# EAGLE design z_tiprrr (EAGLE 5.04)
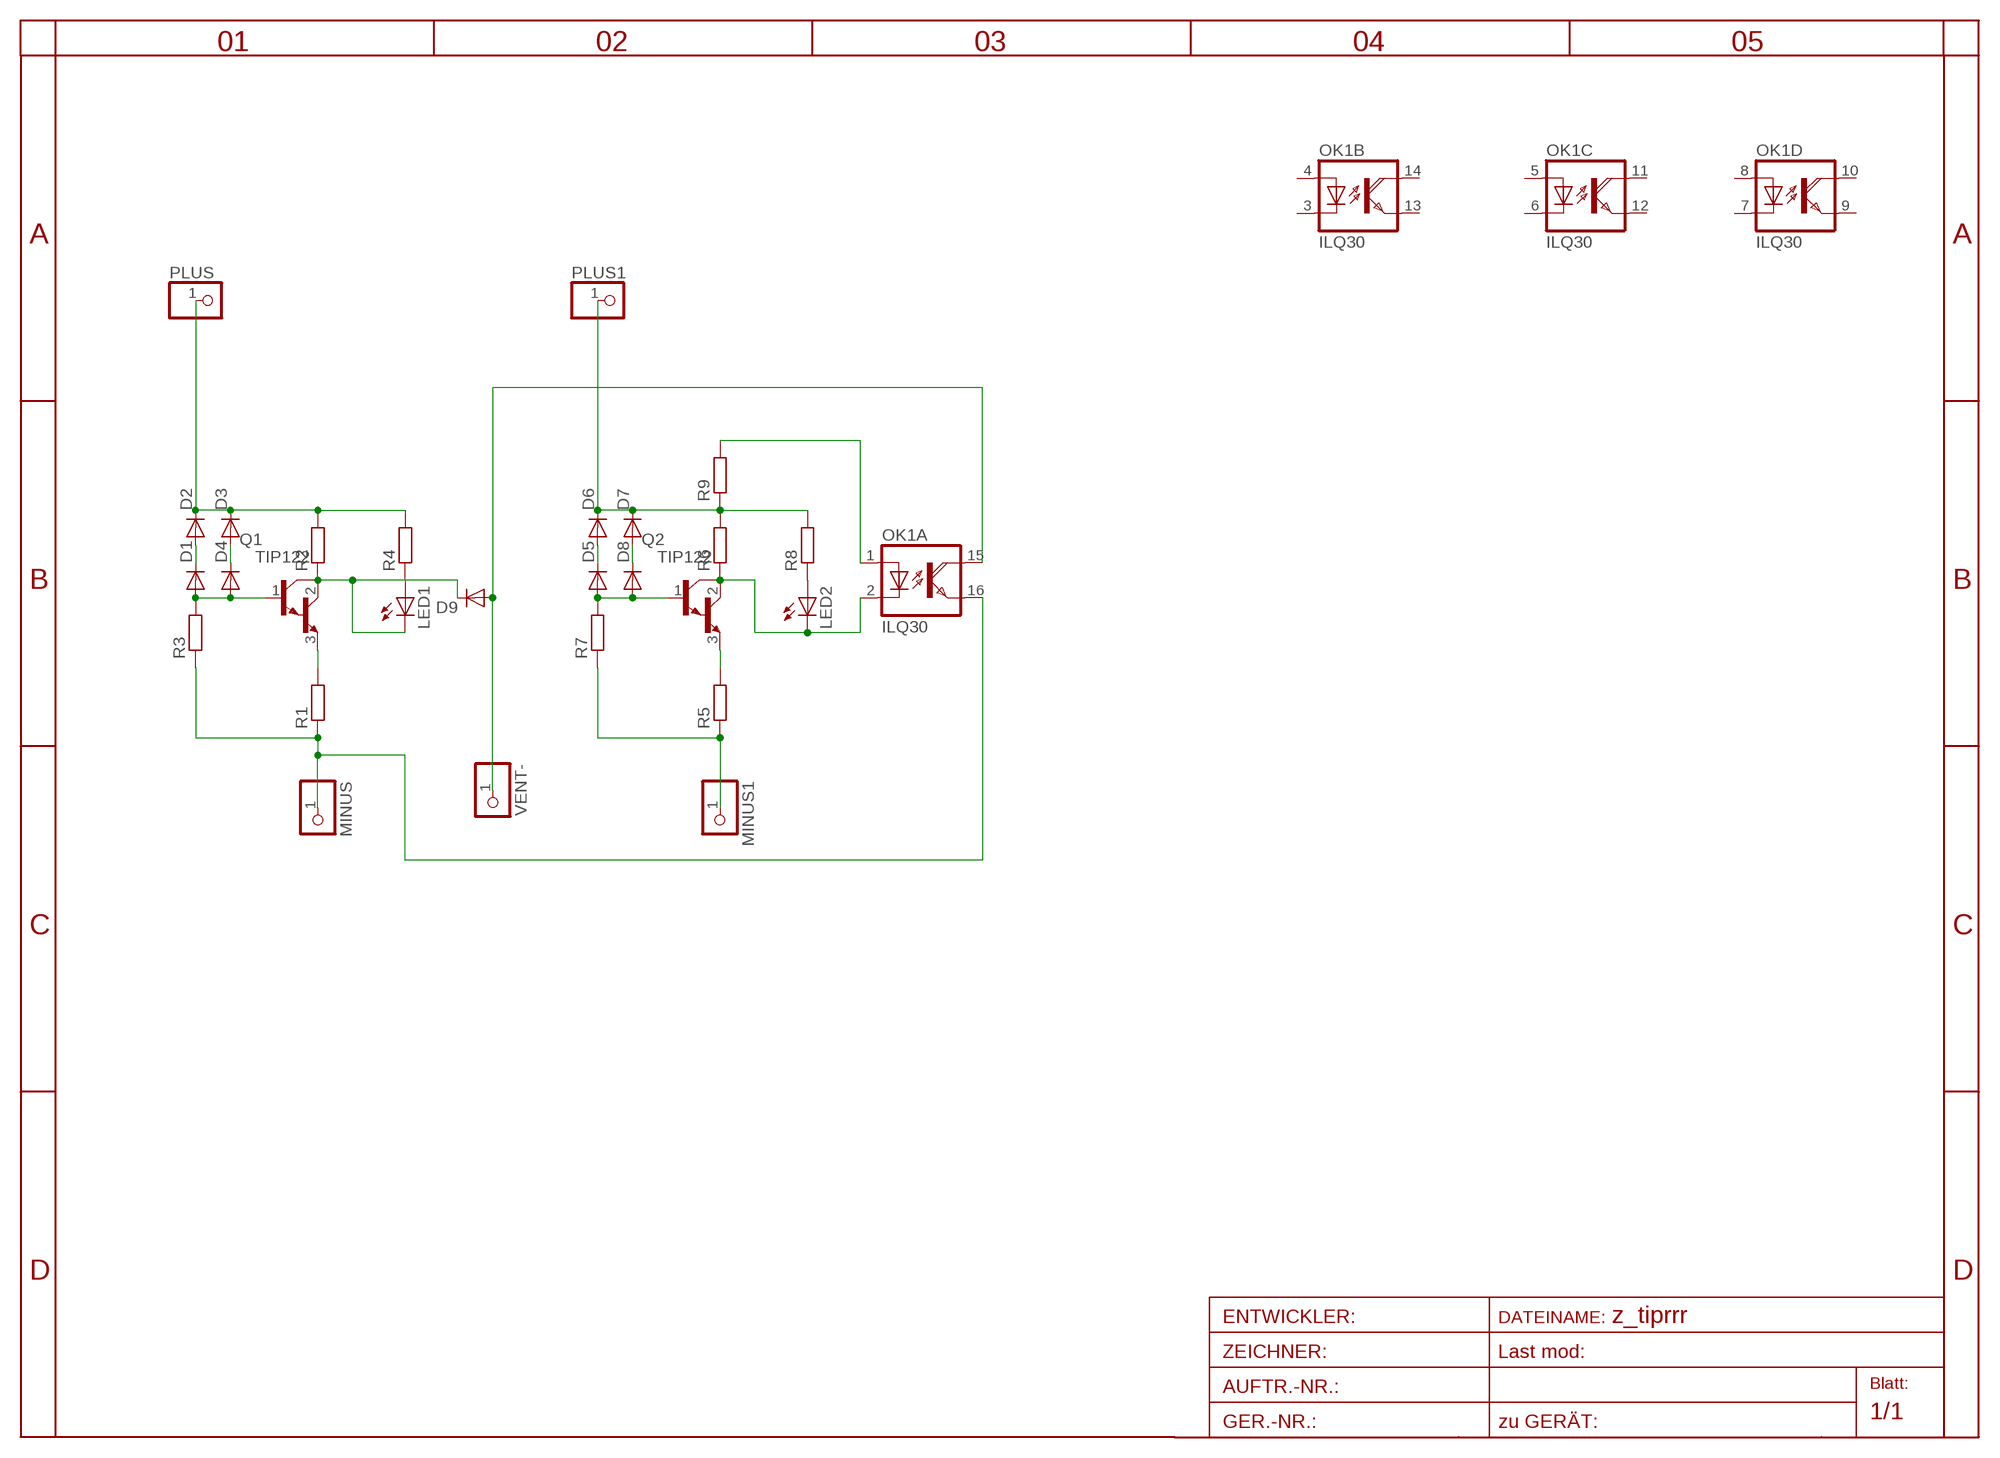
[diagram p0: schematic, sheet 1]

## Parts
D1  DIODE-MINIMELF  [MINIMELF]
D2  DIODE-MINIMELF  [MINIMELF]
D3  DIODE-D-2.5  [D-2.5]
D4  DIODE-D-2.5  [D-2.5]
D5  DIODE-MINIMELF  [MINIMELF]
D6  DIODE-MINIMELF  [MINIMELF]
D7  DIODE-D-2.5  [D-2.5]
D8  DIODE-D-2.5  [D-2.5]
D9  DIODE-MINIMELF  [MINIMELF]
LED1  LED3MM  [LED3MM]
LED2  LED3MM  [LED3MM]
MINUS  PINHD-1X1  [1X01]
MINUS1  PINHD-1X1  [1X01]
OK1  ILQ30  [DIL16]
PLUS  PINHD-1X1  [1X01]
PLUS1  PINHD-1X1  [1X01]
Q1  TIP122  [TO220]
Q2  TIP122  [TO220]
R1  R-EU_M3216  [M3216]
R2  R-EU_M3216  [M3216]
R3  R-EU_R0805  [R0805]
R4  R-EU_M0805  [M0805]
R5  R-EU_M3216  [M3216]
R6  R-EU_M3216  [M3216]
R7  R-EU_R0805  [R0805]
R8  R-EU_M3216  [M3216]
R9  R-EU_M0805  [M0805]
VENT-  PINHD-1X1  [1X01]

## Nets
N$1: D3.A D4.C
N$2: D1.C D2.A
N$3: OK1.1(A:A) R9.2
N$4: D1.A D4.A Q1.1(B) R3.2
N$5: LED1.A R4.1
N$6: MINUS.1 OK1.16(A:EMI) R1.1 R3.1
N$7: Q1.3(E) R1.2
N$8: D9.A OK1.15(A:COL) VENT-.1
N$9: MINUS1.1 R5.1 R7.1
N$10: D5.C D6.A
N$11: D5.A D8.A Q2.1(B) R7.2
N$12: D7.A D8.C
N$13: LED2.K(C) OK1.2(A:C) Q2.2(C) R6.1
N$14: Q2.3(E) R5.2
N$15: LED2.A R8.1
N$16: D9.C LED1.K(C) Q1.2(C) R2.1
PLS: D2.C D3.C PLUS.1 R2.2 R4.2
PLS1: D6.C D7.C PLUS1.1 R6.2 R8.2 R9.1
Unconnected: OK1.3(B:C) OK1.4(B:A) OK1.5(C:A) OK1.6(C:C) OK1.7(D:C) OK1.8(D:A) OK1.9(D:EMI) OK1.10(D:COL) OK1.11(C:COL) OK1.12(C:EMI) OK1.13(B:EMI) OK1.14(B:COL)

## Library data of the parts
D1-D9 = diode-1:DIODE-: DIODE
LED1 LED2 = led:LED: LED
MINUS MINUS1 PLUS PLUS1 VENT- = pinhead:PINHD-1X1: PIN HEADER
OK1 = optocoupler:ILQ30: SIEMENS OPTO COUPLER
Q1 Q2 = transistor-npn:TIP122*: NPN Darlington Transistor
R1-R9 = rcl:R-EU_: RESISTOR, European symbol

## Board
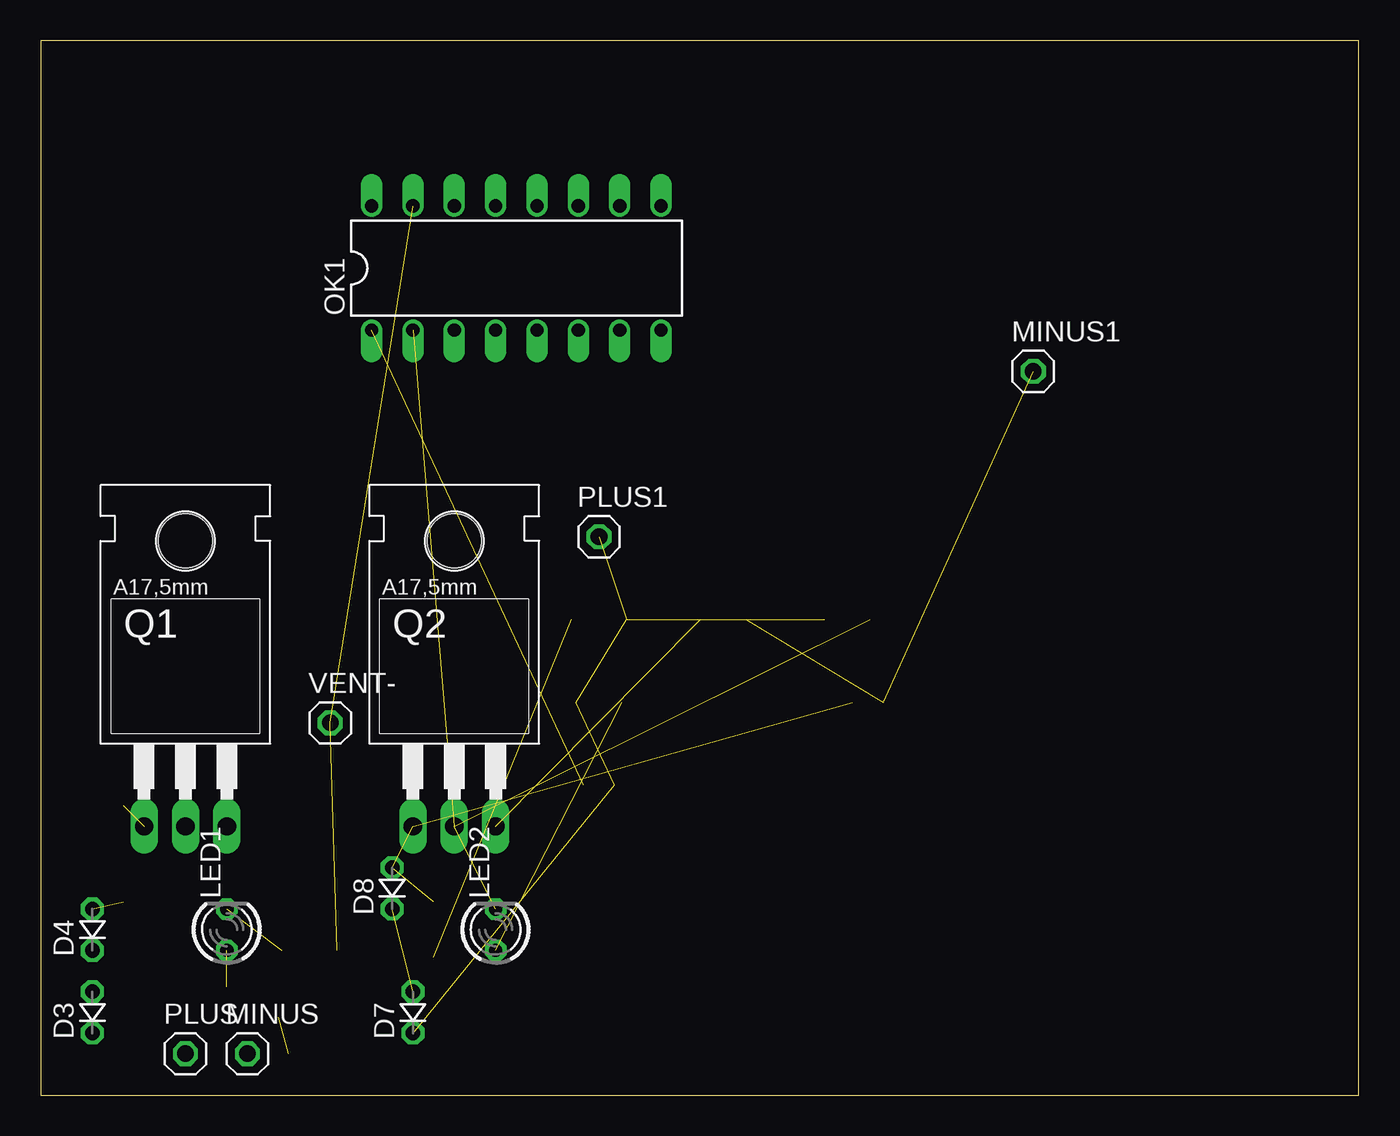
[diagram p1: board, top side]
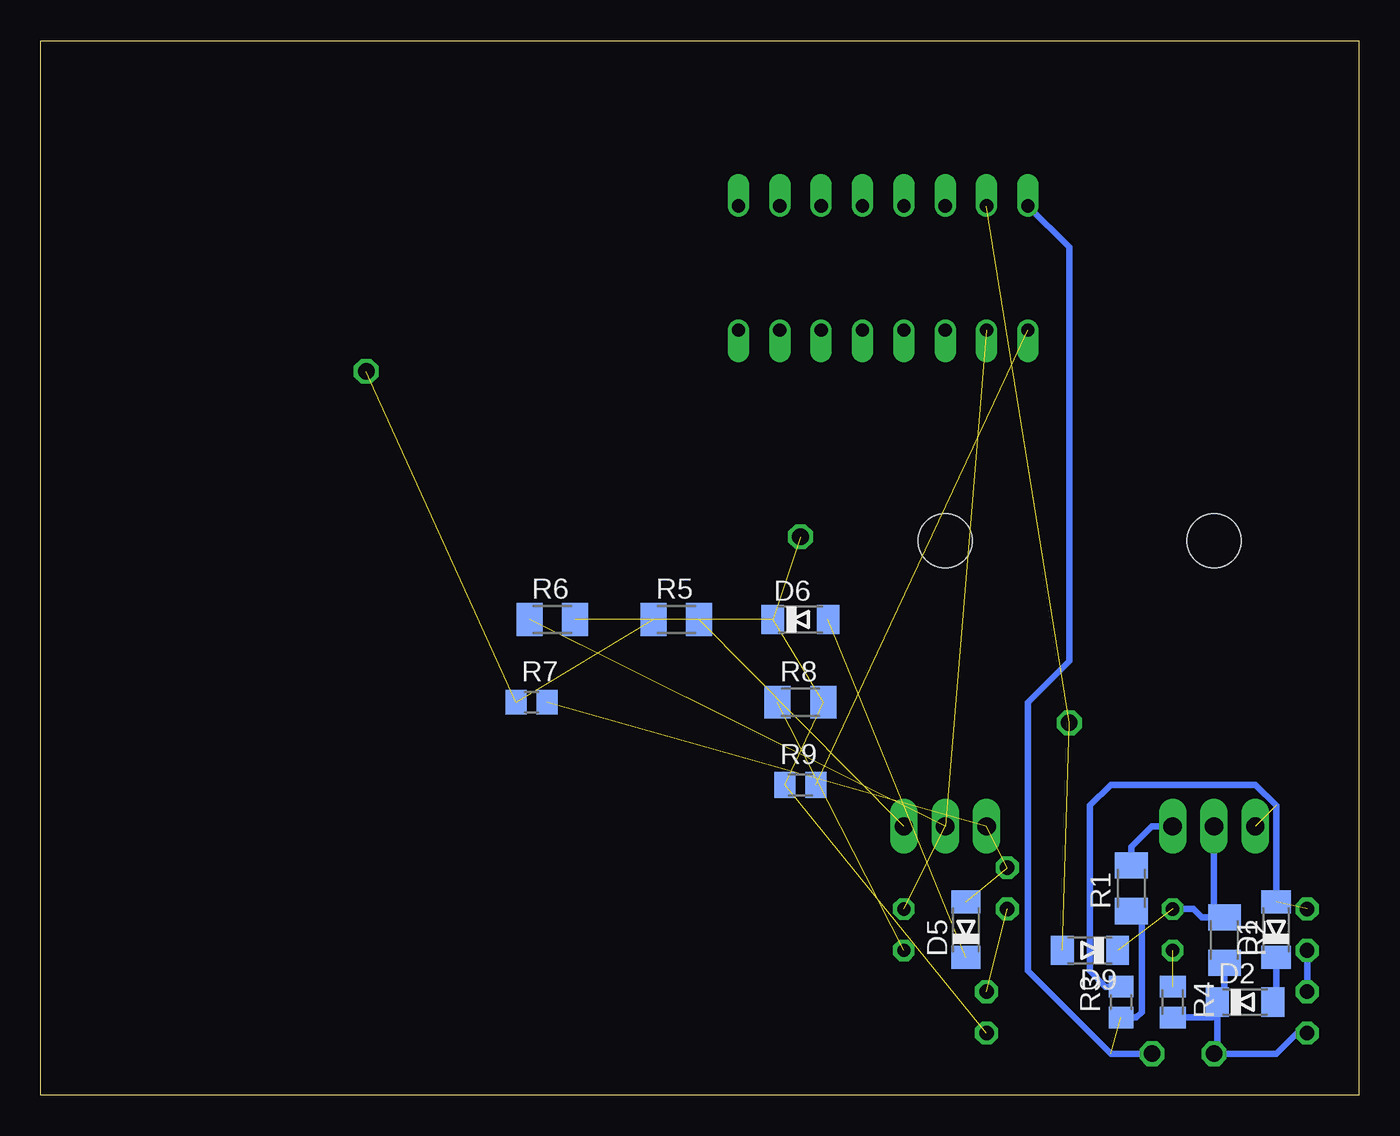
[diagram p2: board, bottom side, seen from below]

Size 80.95 x 64.76 mm. Coordinates in mm from the lower left corner, seen from the top.
Outline: 0,0 80.95,0 80.95,64.76 0,64.76 0,0
Copper layers (1*16): Top 0.035mm / dielectric 1.5mm / Bottom 0.035mm
Design rules "default": minimum track width 10mil, minimum drill 24mil, track to track 8mil, track to pad 8mil, pad to pad 8mil, via to via 8mil, smd to smd 8mil, copper to edge 40mil, drill to drill 8mil, minimum pad ring 10mil, minimum via ring 8mil, stop-mask expansion 4mil, vias tented up to drill 0mil, thermal gap 10mil

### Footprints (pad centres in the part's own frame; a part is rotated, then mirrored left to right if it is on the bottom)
MINIMELF = smd 1.4 x 1.8: A 1.7,0; C -1.7,0
D-2.5 = drill 0.9 octagon: A 1.27,0; C -1.27,0
LED3MM = drill 0.813 octagon: A -1.27,0; K 1.27,0
1X01 = drill 1.016 octagon: 1 0,0
DIL16 = drill 0.813 offset: 1 -8.89,-3.81; 2 -6.35,-3.81; 3 -3.81,-3.81; 4 -1.27,-3.81; 5 1.27,-3.81; 6 3.81,-3.81; 7 6.35,-3.81; 8 8.89,-3.81; 9 8.89,3.81; 10 6.35,3.81; 11 3.81,3.81; 12 1.27,3.81; 13 -1.27,3.81; 14 -3.81,3.81; 15 -6.35,3.81; 16 -8.89,3.81
TO220 = drill 1.118 long: 1 -2.54,-6.35; 2 0,-6.35; 3 2.54,-6.35 | hole 3.302: 0,11.176
M3216 = smd 1.6 x 2: 1 -1.4,0; 2 1.4,0
R0805 = smd 1.3 x 1.5: 1 -0.95,0; 2 0.95,0
M0805 = smd 1.3 x 1.6: 1 -0.95,0; 2 0.95,0

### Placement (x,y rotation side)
D1  5.08,10.16 90 bottom
D2  6.99,5.71 0 bottom
D3  3.17,5.08 90 top
D4  3.17,10.16 90 top
D5  24.13,10.16 90 bottom
D6  34.29,29.21 0 bottom
D7  22.86,5.08 90 top
D8  21.59,12.7 90 top
D9  16.51,8.89 180 bottom
LED1  11.43,10.16 90 top
LED2  27.94,10.16 90 top
MINUS  12.7,2.54 0 top
MINUS1  60.96,44.45 0 top
OK1  29.21,50.8 0 top
PLUS  8.89,2.54 0 top
PLUS1  34.29,34.29 0 top
Q1  8.89,22.86 0 top
Q2  25.4,22.86 0 top
R1  13.97,12.7 90 bottom
R2  8.26,9.53 270 bottom
R3  14.61,5.71 90 bottom
R4  11.43,5.71 270 bottom
R5  41.91,29.21 0 bottom
R6  49.53,29.21 0 bottom
R7  50.8,24.13 0 bottom
R8  34.29,24.13 0 bottom
R9  34.29,19.05 0 bottom
VENT-  17.78,22.86 0 top

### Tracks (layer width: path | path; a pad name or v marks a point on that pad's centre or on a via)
N$1
  Bottom 0.406: D3.A D4.C
N$2
  Bottom 0.406: D1.C 5.08,5.92 D2.A
N$3  (1 unrouted)
N$4  (2 unrouted)
  Bottom 0.406: R3.2 15.55,6.67 16.51,7.62 16.51,17.78 15.24,19.05 6.35,19.05 5.08,17.78 D1.A
N$5  (1 unrouted)
N$6  (1 unrouted)
  Bottom 0.406: R3.1 13.65,4.76 13.34,5.08 13.34,10.66 R1.1 | OK1.16 17.78,52.07 17.78,26.67 20.32,24.13 20.32,7.62 15.24,2.54 MINUS.1
N$7
  Bottom 0.406: R1.2 13.97,15.24 12.7,16.51 Q1.3
N$8  (2 unrouted)
N$9  (2 unrouted)
N$10  (1 unrouted)
N$11  (3 unrouted)
N$12  (1 unrouted)
N$13  (3 unrouted)
N$14  (1 unrouted)
N$15  (1 unrouted)
N$16  (1 unrouted)
  Bottom 0.406: LED1.K 10.16,11.43 9.65,10.93 R2.1 8.89,11.56 Q1.2
PLS
  Bottom 0.406: D3.C 3.81,3.81 5.08,2.54 PLUS.1 8.69,2.75 8.69,5.08 | 8.69,5.08 D2.C 8.26,6.14 R2.2 | R4.2 9,4.76 8.69,5.08
PLS1  (5 unrouted)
